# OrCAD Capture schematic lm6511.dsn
size A
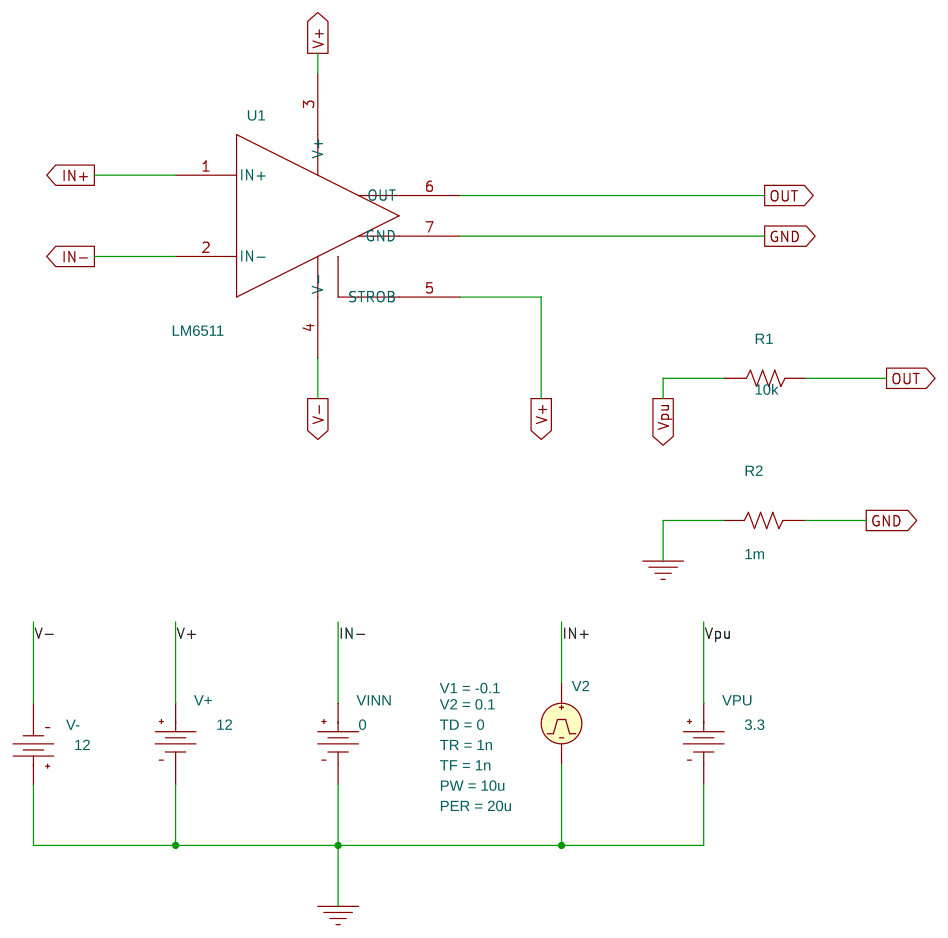
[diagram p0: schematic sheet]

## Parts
R1  10k  [AXRC05]
R2  1m  [AXRC05]
U1  LM6511
V2  VPULSE
V+  VDC
V-  VDC
VINN  VDC
VPU  VDC

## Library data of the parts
R1 R2 = R
U1 = LM6511
V2 = VPULSE: PER: 20u; PW: 10u; TD: 0; TF: 1n; TR: 1n; V1: -0.1; V2: 0.1
V+ V- = VDC: DC: 12
VINN = VDC: DC: 0
VPU = VDC: DC: 3.3

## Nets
GND: R2.1 U1.7(GND)
0: R2.2 V2.2(-) V+.1(-) V-.0(+) VINN.1(-) VPU.1(-)
IN+: U1.1(IN+) V2.1(+)
IN-: U1.2(IN-) VINN.0(+)
OUT: R1.2 U1.6(OUT)
V+: U1.3(V+) U1.5(STROB) V+.0(+)
V-: U1.4(V-) V-.1(-)
Vpu: R1.1 VPU.0(+)
